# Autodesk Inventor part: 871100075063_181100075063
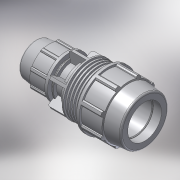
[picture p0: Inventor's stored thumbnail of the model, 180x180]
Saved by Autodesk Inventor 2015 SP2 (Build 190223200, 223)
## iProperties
Created: 2017-02
Part Number: 871100075063_181100075063
Material: PVC-Piping
Description: PLASSON REDUCING COUPLER 75-63
Document SubType Name: Modeling
Designer: KIM
Mass: 92.6774 g
Surface Area: 199.44 cm^2
Volume: 66.1981 cm^3
Density: 1.4 g/cm^3
Appearance: Smooth - White
Author: KIM
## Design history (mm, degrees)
derived "87110.ipt"
feature "Solid1::87110.ipt"
tag "TaggingFeature1"
body "Solid1"
other parameters: "d2" = 75, "d4" = 21.41667, "d5" = 36.71429, "d7" = 132, "d9" = 36.71429, "d11" = 3.67143, "d12" = 105.6, "d13" = 120 deg, "d14" = 105, "d15" = 6 deg, "d16" = 118.8, "d18" = 3.75, "d19" = 35 deg, "d20" = 17.5 deg, "d21" = 122.76, "d23" = 0, "d25" = 360 deg, "d27" = 2.64, "d42" = 56.54, "d46" = 1.5, "d51" = 257, "d52" = 36.71429, "d53" = 8 deg, "d54" = 137, "d56" = 88.2, "d57" = 63, "d58" = 67.5, "d59" = 56.7, "d60" = 101.7, "d61" = 90.4, "d62" = 32.125, "d63" = 46.26, "d64" = 120 deg, "d65" = 113, "d68" = 18.35714, "d74" = 105.09, "d75" = 35 deg, "d76" = 17.5 deg, "d78" = 0, "d80" = 360 deg, "d85" = 2.26, "d88" = 1.26, "d93" = 112, "d94" = 92.4, "d98" = 7.53333, "d99" = 0, "d100" = 5.28, "d102" = 360 deg, "d104" = 2, "d106" = 0, "d107" = 7.53333, "d108" = 0, "d109" = 7.53333, "d110" = 0, "d111" = 3.1, "d112" = 3.1, "d113" = 3.1, "d114" = 2.57171, "d116" = 2.57171, "d119" = 5.14343, "d125" = 116.424, "d_" = 75, "E_" = 132, "H_" = 257, "l_" = 137, "d_1" = 63, "E_1" = 113, "l_1" = 112, "d96" = 9.3, "d115" = 25.71714
